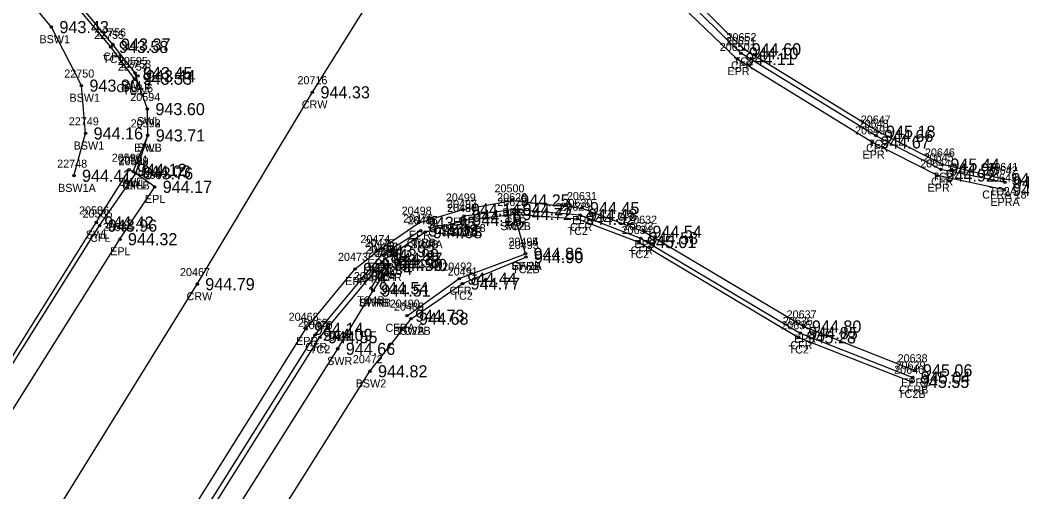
# Model space of a CAD drawing. Extents: x 1576181 to 1577685, y 1099396 to 1101490.
# Drawn here: x 1576527.1 to 1576651.4, y 1099787.6 to 1099846.2 of the extents above; entities that cross this region are included whole.
import ezdxf

# ---------------------------------------------------------------- set-up
doc = ezdxf.new("R2010")
doc.units = 0
for name, color, linetype in [('RD_DTM_BkLn1', 7, 'Continuous'), ('RD_DTM_BkLn2', 7, 'Continuous'), ('RD_EX_Conc', 7, 'Continuous'), ('RD_EX_Conc_txCode', 7, 'Continuous'), ('RD_EX_Road', 7, 'Continuous'), ('RD_EX_Road_txCode', 7, 'Continuous'), ('RD_EX_TX_Conc_ELEV', 7, 'Continuous'), ('RD_EX_TX_Road_ELEV', 7, 'Continuous'), ('RD_HC_Survey_ELEV', 7, 'Continuous'), ('RD_HC_Survey_txCode', 7, 'Continuous'), ('RD_SMD_Locator', 7, 'Continuous')]:
    doc.layers.add(name, color=color, linetype=linetype)

msp = doc.modelspace()

# ---------------------------------------------------------------- linework, layer by layer
at = {"layer": 'RD_DTM_BkLn1'}
msp.add_lwpolyline([(1576435.96, 1099635.47), (1576469.98, 1099685.91), (1576496.51, 1099728.46), (1576522.67, 1099770.85), (1576549.06, 1099813.4), (1576563.36, 1099837.2), (1576575.09, 1099855.95), (1576600.75, 1099898.96), (1576625.57, 1099942.14), (1576652.37, 1099988.91), (1576675.03, 1100029.12), (1576699.51, 1100072.44), (1576723.52, 1100115.7), (1576748.08, 1100158.53), (1576774.13, 1100203.85), (1576797.97, 1100246.52), (1576822.46, 1100289.82), (1576846.93, 1100333.35), (1576871.37, 1100376.46), (1576888.27, 1100406.22)], dxfattribs=at)
at = {"layer": 'RD_DTM_BkLn2'}
for points in [[(1576541.28, 1099838.89), (1576538.34, 1099842.83), (1576526.35, 1099857.06), (1576486.99, 1099904.04), (1576466.33, 1099928.97)], [(1576649.12, 1099826.44), (1576641.55, 1099828.24), (1576633.56, 1099832.32), (1576616.89, 1099842.54), (1576609.51, 1099849.9), (1576607.31, 1099853.68), (1576605.3, 1099859.42)], [(1576582.2, 1099821.36), (1576588.44, 1099822.1), (1576596.27, 1099821.51), (1576603.88, 1099818.63), (1576623.69, 1099806.8), (1576637.76, 1099801.28)], [(1576453.65, 1099622.74), (1576484.93, 1099677.43), (1576510.27, 1099720.56), (1576537.09, 1099763.56), (1576564.3, 1099806.82), (1576572.37, 1099816.55), (1576577.32, 1099819.84)], [(1576572.07, 1099816.2), (1576572.41, 1099815.8), (1576570.62, 1099812.9)], [(1576575.6, 1099809.12), (1576581.99, 1099813.47), (1576589.86, 1099816.76)]]:
    msp.add_lwpolyline(points, dxfattribs=at)
at = {"layer": 'RD_EX_Conc'}
for p, q in [((1576577.32, 1099819.84), (1576582.2, 1099821.36)), ((1576589.81, 1099817.17), (1576588.44, 1099822.1))]:
    msp.add_line(p, q, dxfattribs=at)
for points in [[(1576541.7, 1099839.21), (1576538.6, 1099843.13), (1576526.76, 1099857.36), (1576526.76, 1099857.36), (1576487.52, 1099904.47), (1576466.73, 1099929.4)], [(1576533.76, 1099826.85), (1576535.2, 1099832.1), (1576534.68, 1099838.03), (1576530.96, 1099845.29), (1576523.35, 1099854.41), (1576494.71, 1099889.1)], [(1576649.32, 1099826.02), (1576641.38, 1099827.63), (1576633.3, 1099831.81), (1576616.54, 1099842.04), (1576609.08, 1099849.4), (1576606.84, 1099853.39), (1576604.7, 1099859.17)], [(1576435.66, 1099661.47), (1576443.54, 1099673.97), (1576443.97, 1099673.78), (1576456.79, 1099694.01), (1576456.14, 1099694.19), (1576458.58, 1099697.76), (1576467.89, 1099712.42), (1576470.32, 1099716.02), (1576470.74, 1099715.71), (1576484.32, 1099737.29), (1576483.81, 1099737.74), (1576485.99, 1099741.1), (1576511.43, 1099781.01), (1576536.53, 1099821.05), (1576540.61, 1099827.59), (1576541.13, 1099827.37), (1576542.92, 1099831.85), (1576542.87, 1099835.12), (1576541.33, 1099839.59)], [(1576484.32, 1099737.29), (1576511.76, 1099780.7), (1576536.95, 1099820.66), (1576541.42, 1099827.15)], [(1576582.19, 1099821.87), (1576588.45, 1099822.69), (1576596.57, 1099821.99), (1576604.09, 1099819.1), (1576623.91, 1099807.34), (1576637.88, 1099801.82)], [(1576450.24, 1099618.33), (1576484.56, 1099677.8), (1576510.13, 1099721.55), (1576536.54, 1099763.94), (1576563.69, 1099807.11), (1576571.96, 1099817.02), (1576576.78, 1099820.05)], [(1576575.11, 1099809.49), (1576581.59, 1099814.09), (1576589.81, 1099817.17)], [(1576572.37, 1099816.55), (1576572.94, 1099815.78), (1576570.9, 1099812.6)], [(1576453.65, 1099622.74), (1576455.84, 1099621.56), (1576487.04, 1099675.93), (1576513, 1099720.16), (1576539.03, 1099761.82), (1576566.5, 1099805.38), (1576570.9, 1099812.6)], [(1576460.33, 1099619.05), (1576491.05, 1099673.04), (1576516.28, 1099716.12), (1576543.31, 1099759.42), (1576570.5, 1099802.59), (1576575.6, 1099809.12)]]:
    msp.add_lwpolyline(points, dxfattribs=at)
at = {"layer": 'RD_EX_Road'}
for points in [[(1576649.23, 1099825.1), (1576640.94, 1099826.87), (1576632.86, 1099830.98), (1576616.1, 1099841.33), (1576608.21, 1099848.87), (1576606.02, 1099853.13), (1576603.89, 1099858.95), (1576602.99, 1099864.22), (1576603.41, 1099870.69), (1576607.01, 1099881.11), (1576613.26, 1099891.99), (1576638.31, 1099935.83), (1576663.31, 1099979.53)], [(1576217.78, 1099763.81), (1576263.48, 1099736.46), (1576283.45, 1099724.57), (1576282.38, 1099722.88), (1576302.5, 1099710.8), (1576345.46, 1099684.21), (1576368.62, 1099668.36), (1576383.76, 1099654.94), (1576386.09, 1099656.79), (1576408.06, 1099639.92), (1576408.06, 1099639.92), (1576411.91, 1099642.96), (1576420.57, 1099654.58), (1576428.78, 1099665.98), (1576435.66, 1099661.47), (1576436.12, 1099661.14), (1576438.46, 1099659.42), (1576459.37, 1099692.41), (1576486.6, 1099735.59), (1576512.85, 1099776.73), (1576539.46, 1099818.98), (1576543.78, 1099825.47), (1576541.42, 1099827.15), (1576542.92, 1099831.85)], [(1576450.24, 1099618.33), (1576449.12, 1099618.92), (1576483.24, 1099678.31), (1576508.19, 1099720.98), (1576535.39, 1099764.56), (1576562.56, 1099807.86), (1576568.65, 1099815.29), (1576571.43, 1099817.5), (1576576.56, 1099821.02), (1576582.03, 1099822.66), (1576588.16, 1099823.79), (1576596.81, 1099822.84), (1576604.56, 1099819.9), (1576624.36, 1099808.15), (1576638.14, 1099802.71)]]:
    msp.add_lwpolyline(points, dxfattribs=at)
at = {"layer": 'RD_SMD_Locator'}
for centre in [(1576530.96, 1099845.29), (1576538.6, 1099843.13), (1576538.34, 1099842.83), (1576616.54, 1099842.04), (1576616.89, 1099842.54), (1576616.1, 1099841.33), (1576541.33, 1099839.59), (1576541.28, 1099838.89), (1576541.7, 1099839.21), (1576534.68, 1099838.03), (1576563.36, 1099837.2), (1576542.87, 1099835.12), (1576535.2, 1099832.1), (1576633.56, 1099832.32), (1576542.92, 1099831.85), (1576542.92, 1099831.85), (1576632.86, 1099830.98), (1576633.3, 1099831.81), (1576641.55, 1099828.24), (1576540.61, 1099827.59), (1576541.13, 1099827.37), (1576541.42, 1099827.15), (1576541.42, 1099827.15), (1576641.38, 1099827.63), (1576533.76, 1099826.85), (1576640.94, 1099826.87), (1576649.12, 1099826.44), (1576649.32, 1099826.02), (1576543.78, 1099825.47), (1576649.23, 1099825.1), (1576588.16, 1099823.79), (1576582.03, 1099822.66), (1576588.44, 1099822.1), (1576588.44, 1099822.1), (1576588.45, 1099822.69), (1576596.57, 1099821.99), (1576596.81, 1099822.84), (1576536.53, 1099821.05), (1576576.56, 1099821.02), (1576582.19, 1099821.87), (1576582.2, 1099821.36), (1576582.2, 1099821.36), (1576596.27, 1099821.51), (1576536.95, 1099820.66), (1576576.78, 1099820.05), (1576577.32, 1099819.84), (1576577.32, 1099819.84), (1576604.56, 1099819.9), (1576539.46, 1099818.98), (1576603.88, 1099818.63), (1576604.09, 1099819.1), (1576571.43, 1099817.5), (1576571.96, 1099817.02), (1576589.81, 1099817.17), (1576589.81, 1099817.17), (1576572.07, 1099816.2), (1576572.37, 1099816.55), (1576572.37, 1099816.55), (1576572.41, 1099815.8), (1576572.94, 1099815.78), (1576589.86, 1099816.76), (1576568.65, 1099815.29), (1576549.06, 1099813.4), (1576581.59, 1099814.09), (1576581.99, 1099813.47), (1576570.62, 1099812.9), (1576570.9, 1099812.6), (1576570.9, 1099812.6), (1576575.11, 1099809.49), (1576575.6, 1099809.12), (1576575.6, 1099809.12), (1576562.56, 1099807.86), (1576563.69, 1099807.11), (1576623.91, 1099807.34), (1576624.36, 1099808.15), (1576564.3, 1099806.82), (1576623.69, 1099806.8), (1576566.5, 1099805.38), (1576570.5, 1099802.59), (1576638.14, 1099802.71), (1576637.76, 1099801.28), (1576637.88, 1099801.82)]:
    msp.add_circle(centre, 0.15, dxfattribs=at)

# ---------------------------------------------------------------- texts
at = {"layer": 'RD_EX_Conc_txCode'}
for s, p in [('22755', (1576536.26, 1099843.83)), ('22756', (1576536.5, 1099844.13)), ('20652', (1576614.75, 1099843.54)), ('BSW1', (1576529.48, 1099843.29)), ('20651', (1576614.68, 1099843.04)), ('CFL', (1576537.4, 1099841.13)), ('TC1', (1576537.37, 1099840.83)), ('22754', (1576539.2, 1099839.89)), ('20595', (1576539.21, 1099840.59)), ('22753', (1576539.62, 1099840.21)), ('CFR', (1576615.31, 1099840.04)), ('TC2', (1576615.65, 1099840.54)), ('22750', (1576532.56, 1099839.03)), ('SWLB', (1576539.57, 1099837.59)), ('CFLA 6', (1576539.04, 1099837.21)), ('TC1A', (1576539.83, 1099836.89)), ('20594', (1576540.75, 1099836.12)), ('BSW1', (1576533.2, 1099836.03)), ('22749', (1576533.12, 1099833.1)), ('20593', (1576540.8, 1099832.85)), ('SWL', (1576541.58, 1099833.12)), ('20648', (1576631.16, 1099832.81)), ('20647', (1576631.42, 1099833.32)), ('BSW1', (1576533.72, 1099830.1)), ('SWL', (1576541.63, 1099829.85)), ('TC2', (1576632.32, 1099830.32)), ('20590', (1576538.45, 1099828.59)), ('CFR', (1576632.08, 1099829.81)), ('20645', (1576639.23, 1099828.63)), ('20646', (1576639.39, 1099829.24)), ('22748', (1576531.68, 1099827.85)), ('20591', (1576539.29, 1099828.37)), ('20588', (1576539.3, 1099828.15)), ('20641', (1576647.26, 1099827.44)), ('TC2', (1576640.31, 1099826.24)), ('20642', (1576647.18, 1099827.02)), ('SWL', (1576539.32, 1099825.59)), ('CFLB', (1576539.74, 1099825.15)), ('SWL', (1576539.84, 1099825.37)), ('CFR', (1576640.15, 1099825.63)), ('BSW1A', (1576531.79, 1099824.85)), ('20626', (1576586.29, 1099823.69)), ('CFRA 18', (1576646.5, 1099824.02)), ('TC2A', (1576647.39, 1099824.44)), ('20497', (1576580.07, 1099822.87)), ('20627', (1576586.3, 1099823.1)), ('20628', (1576586.3, 1099823.1)), ('20629', (1576594.13, 1099822.51)), ('20630', (1576594.39, 1099822.99)), ('20586', (1576534.39, 1099822.05)), ('20585', (1576534.83, 1099821.66)), ('20496', (1576580.06, 1099822.36)), ('20487', (1576580.08, 1099822.36)), ('20476', (1576574.63, 1099821.05)), ('20486', (1576575.18, 1099820.84)), ('20485', (1576575.2, 1099820.84)), ('SW2B', (1576586.68, 1099820.1)), ('TC2', (1576587.2, 1099820.1)), ('CFR', (1576587.22, 1099820.69)), ('CFR', (1576595.34, 1099819.99)), ('20633', (1576601.95, 1099820.1)), ('SWL', (1576535.24, 1099819.05)), ('CFL', (1576535.75, 1099818.66)), ('CFRA 18', (1576579.37, 1099819.87)), ('SWRB', (1576580.41, 1099819.36)), ('TC2A', (1576580.47, 1099819.36)), ('TC2', (1576595.03, 1099819.51)), ('20634', (1576601.74, 1099819.63)), ('20475', (1576569.85, 1099818.02)), ('20477', (1576570.25, 1099817.55)), ('20478', (1576570.25, 1099817.55)), ('CFRB', (1576575.07, 1099818.05)), ('SWRA', (1576575.52, 1099817.84)), ('TC2B', (1576575.61, 1099817.84)), ('20494', (1576587.69, 1099818.17)), ('20495', (1576587.69, 1099818.17)), ('20493', (1576587.74, 1099817.76)), ('20479', (1576569.95, 1099817.2)), ('20480', (1576570.25, 1099816.8)), ('20481', (1576571.11, 1099816.78)), ('TC2', (1576602.64, 1099816.63)), ('CFR', (1576602.86, 1099817.1)), ('CFR', (1576570.74, 1099815.02)), ('20492', (1576579.47, 1099815.09)), ('SW2A', (1576588.03, 1099815.17)), ('CFRB', (1576588.11, 1099815.17)), ('20482', (1576568.5, 1099813.9)), ('CFRA 6', (1576569.69, 1099814.55)), ('TC4A', (1576570.34, 1099814.2)), ('TC2', (1576571.12, 1099814.55)), ('TC4', (1576571.17, 1099813.8)), ('CFR', (1576571.71, 1099813.78)), ('20491', (1576580.15, 1099814.47)), ('TC2B', (1576588.14, 1099814.76)), ('20483', (1576568.78, 1099813.6)), ('20484', (1576568.78, 1099813.6)), ('CFR', (1576580.36, 1099812.09)), ('TC2', (1576580.74, 1099811.47)), ('TC4B', (1576568.9, 1099810.9)), ('SWRB', (1576569.11, 1099810.6)), ('CFRB', (1576569.2, 1099810.6)), ('20490', (1576572.95, 1099810.49)), ('20488', (1576573.48, 1099810.12)), ('20489', (1576573.48, 1099810.12)), ('20469', (1576561.55, 1099808.11)), ('20470', (1576562.14, 1099807.82)), ('CFRA 6', (1576572.43, 1099807.49)), ('20635', (1576621.55, 1099807.8)), ('20636', (1576621.74, 1099808.34)), ('20471', (1576564.67, 1099806.38)), ('BSW2B', (1576573.36, 1099807.12)), ('TC2A', (1576573.86, 1099807.12)), ('CFR', (1576562.46, 1099805.11)), ('CFR', (1576622.68, 1099805.34)), ('TC2', (1576563.05, 1099804.82)), ('TC2', (1576622.45, 1099804.8)), ('SWR', (1576565.19, 1099803.38)), ('20472', (1576568.38, 1099803.59)), ('20639', (1576635.74, 1099802.82)), ('20640', (1576635.58, 1099802.28)), ('BSW2', (1576568.73, 1099800.59)), ('TC2B', (1576636.04, 1099799.28)), ('CFRB', (1576636.18, 1099799.82))]:
    msp.add_text(s, height=1, dxfattribs=at).set_placement(p)
at = {"layer": 'RD_EX_Road_txCode'}
for s, p in [('20650', (1576613.92, 1099842.33)), ('EPR', (1576614.88, 1099839.33)), ('20592', (1576540.8, 1099832.85)), ('20649', (1576630.72, 1099831.98)), ('EPLB', (1576541.24, 1099829.85)), ('EPR', (1576631.64, 1099828.98)), ('20589', (1576539.3, 1099828.15)), ('20644', (1576638.8, 1099827.87)), ('20587', (1576541.66, 1099826.47)), ('20643', (1576647.09, 1099826.1)), ('EPL', (1576540.21, 1099825.15)), ('EPR', (1576639.72, 1099824.87)), ('20499', (1576579.92, 1099823.66)), ('20500', (1576585.96, 1099824.79)), ('20631', (1576594.95, 1099823.84)), ('EPL', (1576542.57, 1099823.47)), ('EPRA', (1576647.51, 1099823.1)), ('20498', (1576574.44, 1099822.02)), ('EPR', (1576586.93, 1099821.79)), ('20584', (1576537.34, 1099819.98)), ('EPR', (1576580.81, 1099820.66)), ('EPR', (1576595.58, 1099820.84)), ('20632', (1576602.42, 1099820.9)), ('EPR', (1576575.33, 1099819.02)), ('20474', (1576569.32, 1099818.5)), ('EPR', (1576603.33, 1099817.9)), ('EPL', (1576538.25, 1099816.98)), ('20473', (1576566.53, 1099816.29)), ('EPR', (1576570.21, 1099815.5)), ('EPR', (1576567.42, 1099813.29)), ('20468', (1576560.41, 1099808.86)), ('20637', (1576622.22, 1099809.15)), ('EPR', (1576561.33, 1099805.86)), ('EPR', (1576623.13, 1099806.15)), ('20638', (1576636, 1099803.71)), ('EPRB', (1576636.44, 1099800.71))]:
    msp.add_text(s, height=1, dxfattribs=at).set_placement(p)
at = {"layer": 'RD_EX_TX_Conc_ELEV'}
for s, p in [('943.43', (1576531.96, 1099844.54)), ('943.58', (1576539.34, 1099842.08)), ('943.37', (1576539.6, 1099842.38)), ('944.60', (1576617.89, 1099841.79)), ('944.10', (1576617.54, 1099841.29)), ('943.53', (1576542.28, 1099838.14)), ('943.45', (1576542.33, 1099838.84)), ('943.44', (1576542.7, 1099838.46)), ('943.80', (1576535.68, 1099837.28)), ('943.60', (1576543.87, 1099834.37)), ('944.16', (1576536.2, 1099831.35)), ('943.71', (1576543.92, 1099831.1)), ('944.66', (1576634.3, 1099831.06)), ('945.18', (1576634.56, 1099831.57)), ('944.12', (1576541.61, 1099826.84)), ('944.95', (1576642.38, 1099826.88)), ('945.44', (1576642.55, 1099827.49)), ('944.41', (1576534.76, 1099826.1)), ('944.03', (1576542.13, 1099826.62)), ('943.76', (1576542.42, 1099826.4)), ('945.54', (1576650.12, 1099825.69)), ('945.04', (1576650.32, 1099825.27)), ('944.27', (1576589.45, 1099821.94)), ('944.16', (1576583.19, 1099821.12)), ('944.72', (1576589.44, 1099821.35)), ('944.72', (1576589.44, 1099821.35)), ('944.92', (1576597.27, 1099820.76)), ('944.48', (1576597.57, 1099821.24)), ('944.42', (1576537.53, 1099820.3)), ('943.96', (1576537.95, 1099819.91)), ('944.18', (1576583.2, 1099820.61)), ('944.18', (1576583.2, 1099820.61)), ('944.03', (1576577.78, 1099819.3)), ('944.08', (1576578.32, 1099819.09)), ('944.08', (1576578.32, 1099819.09)), ('944.58', (1576605.09, 1099818.35)), ('945.01', (1576604.88, 1099817.88)), ('943.99', (1576572.96, 1099816.27)), ('944.37', (1576573.37, 1099815.8)), ('944.37', (1576573.37, 1099815.8)), ('944.86', (1576590.81, 1099816.42)), ('944.86', (1576590.81, 1099816.42)), ('944.90', (1576590.86, 1099816.01)), ('944.38', (1576573.07, 1099815.45)), ('944.59', (1576573.41, 1099815.05)), ('944.40', (1576573.94, 1099815.03)), ('944.44', (1576582.59, 1099813.34)), ('944.54', (1576571.62, 1099812.15)), ('944.77', (1576582.99, 1099812.72)), ('944.51', (1576571.9, 1099811.85)), ('944.51', (1576571.9, 1099811.85)), ('944.73', (1576576.11, 1099808.74)), ('944.68', (1576576.6, 1099808.37)), ('944.68', (1576576.6, 1099808.37)), ('944.09', (1576564.69, 1099806.36)), ('944.55', (1576565.3, 1099806.07)), ('945.28', (1576624.69, 1099806.05)), ('944.85', (1576624.91, 1099806.59)), ('944.66', (1576567.5, 1099804.63)), ('944.82', (1576571.5, 1099801.84)), ('945.04', (1576638.88, 1099801.07)), ('945.55', (1576638.76, 1099800.53))]:
    msp.add_text(s, height=1.5, dxfattribs=at).set_placement(p)
at = {"layer": 'RD_EX_TX_Road_ELEV'}
for s, p in [('944.11', (1576617.1, 1099840.58)), ('943.71', (1576543.92, 1099831.1)), ('944.67', (1576633.86, 1099830.23)), ('943.76', (1576542.42, 1099826.4)), ('944.92', (1576641.94, 1099826.12)), ('944.17', (1576544.78, 1099824.72)), ('945.02', (1576650.23, 1099824.35)), ('944.14', (1576583.03, 1099821.91)), ('944.25', (1576589.16, 1099823.04)), ('944.45', (1576597.81, 1099822.09)), ('943.95', (1576577.56, 1099820.27)), ('944.32', (1576540.46, 1099818.23)), ('944.54', (1576605.56, 1099819.15)), ('943.93', (1576572.43, 1099816.75)), ('943.94', (1576569.65, 1099814.54)), ('944.14', (1576563.56, 1099807.11)), ('944.80', (1576625.36, 1099807.4)), ('945.06', (1576639.14, 1099801.96))]:
    msp.add_text(s, height=1.5, dxfattribs=at).set_placement(p)
at = {"layer": 'RD_HC_Survey_ELEV'}
for s, p in [('944.33', (1576564.36, 1099836.45)), ('944.79', (1576550.06, 1099812.65))]:
    msp.add_text(s, height=1.5, dxfattribs=at).set_placement(p)
at = {"layer": 'RD_HC_Survey_txCode'}
for s, p in [('20716', (1576561.5, 1099838.2)), ('CRW', (1576562.04, 1099835.2)), ('20467', (1576546.92, 1099814.4)), ('CRW', (1576547.74, 1099811.4))]:
    msp.add_text(s, height=1, dxfattribs=at).set_placement(p)

doc.saveas('drawing.dxf')
